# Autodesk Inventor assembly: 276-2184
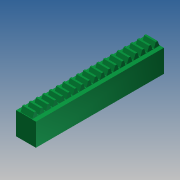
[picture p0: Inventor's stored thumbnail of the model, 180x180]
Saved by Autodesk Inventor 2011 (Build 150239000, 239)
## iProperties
Company: Autodesk Inc.
Created: 2007-09
Part Number: 276-2184
Document SubType Name: Assembly
Catalog Web Link: http://www.vexrobotics.com/products/accessories/motion/276-2184.html
Description: This kit provides several options for advanced motion. These parts allow advanced mechanical Vex designers to create new ingeni
Vendor: Innovation First, Inc.
Designer: Autodesk Inc.
Title: VEX Robotics Kit of Parts
Author: Autodesk Inc.
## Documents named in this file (3)
- C:\Data Folder\VEX KOP 2010\VEX Parts Kit\Motion\Rack_Assembly.iam
- C:\Data Folder\VEX KOP 2010\VEX Parts Kit\Motion\INSERT-NUT.ipt
- C:\Data Folder\VEX KOP 2010\VEX Parts Kit\Motion\RACK.ipt
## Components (4 placed, 2 different names)
1. RACK — Insert:1, Insert:2, Insert:3
2. INSERT-NUT — Insert:1
3. INSERT-NUT — Insert:3
4. INSERT-NUT — Insert:2
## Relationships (3: Insert 3)
- Insert:1: RACK ↔ INSERT-NUT
- Insert:2: RACK ↔ INSERT-NUT
- Insert:3: RACK ↔ INSERT-NUT
